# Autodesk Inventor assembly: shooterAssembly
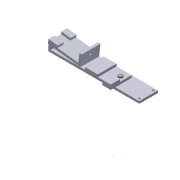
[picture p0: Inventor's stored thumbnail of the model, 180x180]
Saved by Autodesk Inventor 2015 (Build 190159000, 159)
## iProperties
Created: 2016-07
Part Number: shooterAssembly
Document SubType Name: Assembly
Designer: user
Author: user
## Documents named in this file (13)
- G:\projects\Webshooters (Not the white stuff that shoots out of boys)\mockups\foamHolder\shooterAssembly.iam
- G:\projects\Webshooters (Not the white stuff that shoots out of boys)\mockups\foamHolder\base.ipt
- G:\projects\Webshooters (Not the white stuff that shoots out of boys)\mockups\foamHolder\dartBoard.ipt
- G:\projects\Webshooters (Not the white stuff that shoots out of boys)\mockups\foamHolder\motorMount1.ipt
- G:\projects\Webshooters (Not the white stuff that shoots out of boys)\mockups\foamHolder\motorMount2.ipt
- G:\projects\Webshooters (Not the white stuff that shoots out of boys)\mockups\foamHolder\dartBackBoard.ipt
- G:\projects\Webshooters (Not the white stuff that shoots out of boys)\mockups\foamHolder\baseProp.ipt
- G:\projects\Webshooters (Not the white stuff that shoots out of boys)\mockups\foamHolder\dartHolder.ipt
- G:\projects\Webshooters (Not the white stuff that shoots out of boys)\mockups\foamHolder\baseBench.ipt
- G:\projects\Webshooters (Not the white stuff that shoots out of boys)\mockups\foamHolder\hardStop.ipt
- G:\projects\Webshooters (Not the white stuff that shoots out of boys)\mockups\foamHolder\motorMount3.ipt
- C:\Users\user\Documents\Inventor\Content Center Files\R2015\en-US\AS 2465(2)\AS 2465 - 1_4 x 1_2  UNC.ipt
- C:\Users\user\Documents\Inventor\Content Center Files\R2015\en-US\AS 2465(1)\AS 2465 - 1_4  UNC(1).ipt
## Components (12 placed, 12 different names)
1. base:1 — Insert:1, Mate:1, Flush:1, Flush:6, Flush:7, Mate:3, Flush:12, Flush:13, Flush:14, Flush:15
2. dartBoard:1 — Mate:1, Flush:1, Mate:2, Mate:4, Flush:8, Flush:9, Flush:10, Flush:11
3. motorMount1:1
4. motorMount2:1 — Insert:1, Mate:5, Flush:18, Flush:19, Flush:20
5. dartBackBoard:1 — Mate:4, Flush:8, Flush:9, Flush:10
6. baseProp:1 — Flush:6, Mate:2, Flush:7, Mate:3
7. dartHolder:1 — Flush:11, Flush:12
8. baseBench:1 — Flush:13, Flush:14, Flush:15, Mate:5, Mate:6, Flush:16, Flush:17
9. hardStop:1 — Mate:6, Flush:16, Flush:17
10. motorMount3:1 — Flush:18, Flush:19, Flush:20
11. AS 2465 - Inch 1/4 x 1/2  UNC:1
12. AS 2465 - Inch 1/4  UNC:1
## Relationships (23: Flush 16, Mate 6, Insert 1)
- Insert:1: base:1 ↔ motorMount2:1
- Mate:1: base:1 ↔ dartBoard:1
- Flush:1: base:1 ↔ dartBoard:1
- Flush:6: base:1 ↔ baseProp:1
- Mate:2: dartBoard:1 ↔ baseProp:1
- Flush:7: base:1 ↔ baseProp:1
- Mate:3: base:1 ↔ baseProp:1
- Mate:4: dartBoard:1 ↔ dartBackBoard:1
- Flush:8: dartBoard:1 ↔ dartBackBoard:1
- Flush:9: dartBoard:1 ↔ dartBackBoard:1
- Flush:10: dartBoard:1 ↔ dartBackBoard:1
- Flush:11: dartBoard:1 ↔ dartHolder:1
- Flush:12: base:1 ↔ dartHolder:1
- Flush:13: base:1 ↔ baseBench:1
- Flush:14: base:1 ↔ baseBench:1
- Flush:15: base:1 ↔ baseBench:1
- Mate:5: motorMount2:1 ↔ baseBench:1
- Mate:6: baseBench:1 ↔ hardStop:1
- Flush:16: baseBench:1 ↔ hardStop:1
- Flush:17: baseBench:1 ↔ hardStop:1
- Flush:18: motorMount2:1 ↔ motorMount3:1
- Flush:19: motorMount2:1 ↔ motorMount3:1
- Flush:20: motorMount2:1 ↔ motorMount3:1
